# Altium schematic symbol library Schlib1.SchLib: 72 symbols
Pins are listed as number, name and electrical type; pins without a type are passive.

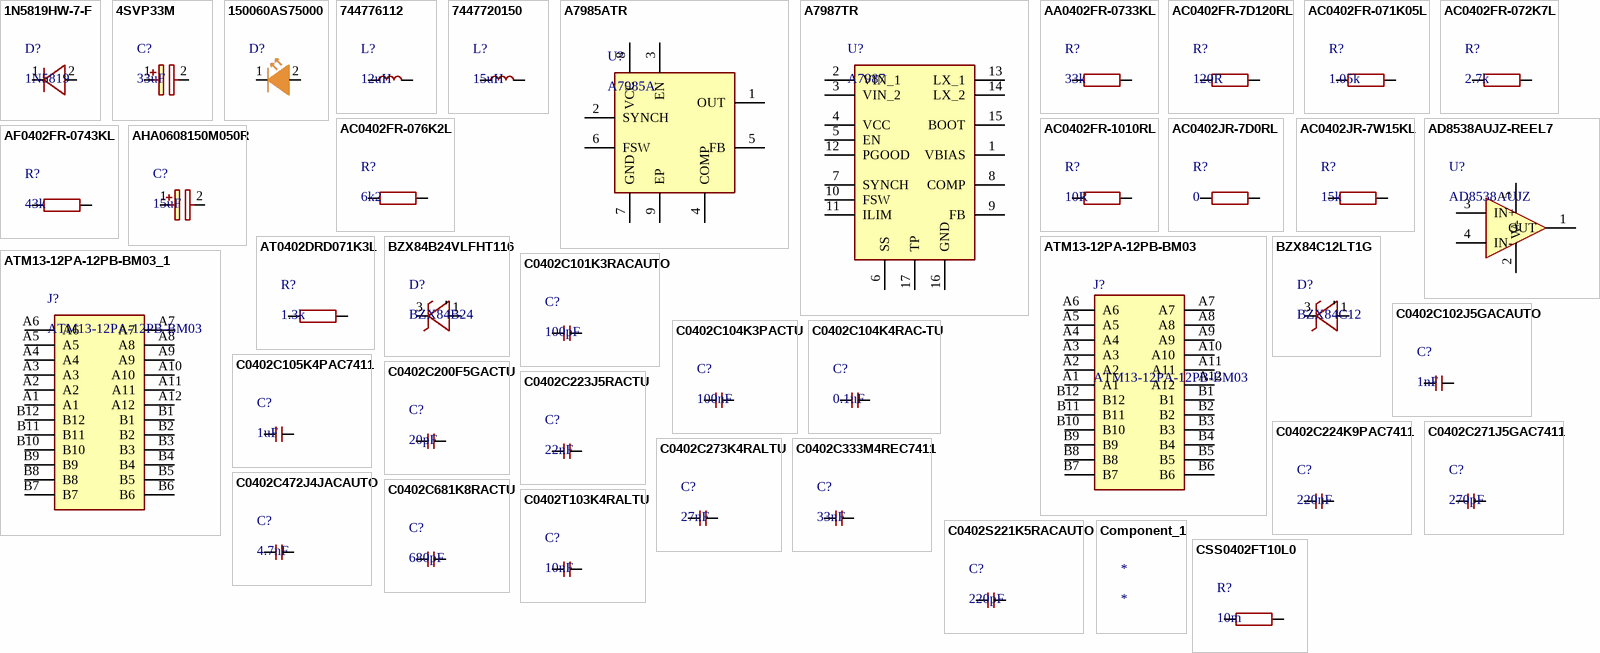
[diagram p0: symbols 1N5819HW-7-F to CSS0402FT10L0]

## 1N5819HW-7-F
designator D?, comment 1N5819
Rectifier Diode, Schottky, 1 Phase, 1 Element, 1A, 40V V(RRM), Silicon; Manufacturer: Diodes; Manufacturer Part Number: 1N5819HW-7-F; Package Body Material: Plastic; Number of Elements: 1; Max Power Dissipation: 450mW; Forward Voltage: 320mV; Non-rep Pk Forward Current-Max: 25A; Time @ Peak Reflow Temperature-Max (s): 40s; Qualification Status: Not Qualified
footprint SOD3716X125N
pins: 1 K, 2 A

## 4SVP33M
designator C?, comment 33uF
Aluminum Electrolytic Capacitor, Polarized, Aluminum (solid Polymer), 4V, 20% +Tol, 20% -Tol, 33uF, Surface Mount, 1717; Manufacturer: Panasonic; Manufacturer Part Number: 4SVP33M; Manufacturer Series: SVP; Dielectric Material: Aluminium; ESR (Equivalent Series Resistance): 200mR; Leakage Current: 66uA; Ripple Current: 37mA; Tan Delta: 0.15
footprint 10SVPS10M
pins: 1 +, 2

## 150060AS75000
designator D?  (value not drawn)
Single Color LED, Amber, Water Clear, 1.1mm; Manufacturer: Wurth Electronics
footprint LED-0603
pins: 1 K, 2 A

## 744776112
designator L?, comment 12uH
General Purpose Inductor, 12uH, 20%, 1 Element, Nickel-zinc Ferrite-Core, SMD, 3935; Manufacturer: Wurth Electronics; Manufacturer Part Number: 744776112; DC Resistance (DCR): 70mR; Inductor Application: POWER INDUCTOR; Channels: 1; Max Current Rating: 2.72A; Shape/Size Description: RECTANGULAR PACKAGE; Shielding: Unshielded; Test Frequency: 1kHz; Self Resonant Frequency: 20MHz
footprint WE-PD2_105455
pins: 1, 2

## 7447720150
designator L?, comment 15uH
Data Line Filter, 1 Function(s), 2.4A; Manufacturer: Wurth Electronics; Manufacturer Part Number: 7447720150; DC Resistance-Max: 45mR; Channels: 1
footprint WE-TI_809589
pins: 1, 2

## A7985ATR
designator U?, comment A7985A
Switching Regulator, Voltage-mode, 3.5A, 275kHz Switching Freq-Max, PDSO8; Manufacturer: STMicroelectronics; Manufacturer Part Number: A7985ATR; Package Body Material: Plastic; Package Equivalence Code: SOP8,.25; Control Technique: PULSE WIDTH MODULATION; Max Supply Voltage: 38V; Min Input Voltage: 4.5V; Nominal Supply Voltage: 12V; Channels: 1; Switcher Configuration: BUCK; Qualification Status: Not Qualified
footprint SOIC127P600X170-9N
pins: 1 OUT, 2 SYNCH, 3 EN, 4 COMP, 5 FB, 6 FSW, 7 GND, 8 VCC, 9 EP

## A7987TR
designator U?, comment A7987
Switching Regulator, Voltage-mode, 4.4A, 1650kHz Switching Freq-Max, PDSO16; Manufacturer: STMicroelectronics; Manufacturer Part Number: A7987TR
footprint SOP65P640X120-17N
pins: 1 VBIAS, 2 VIN_1, 3 VIN_2, 4 VCC, 5 EN, 6 SS, 7 SYNCH, 8 COMP, 9 FB, 10 FSW, 11 ILIM, 12 PGOOD, 13 LX_1, 14 LX_2, 15 BOOT, 16 GND, 17 TP

## AA0402FR-0733KL
designator R?, comment 33k
Fixed Resistor, Metal Glaze/thick Film, 0.0625W, 33000ohm, 50V, 1% +/-Tol, 150ppm/Cel, Surface Mount, 0402; Manufacturer: Yageo; Manufacturer Part Number: AA0402FR-0733KL; Additional Feature: LASER TRIMMABLE; Power: 62.5mW; Rated Temperature: 70°C; Value: 33kR; Temperature Coefficient (ppm/Cel): 150; Package Height: 0.32mm; Package Length: 1mm; Package Width: 0.5mm; Reference Standard: AEC-Q200
footprint R0402
pins: 1, 2

## AC0402FR-7D120RL
designator R?, comment 120R
Fixed Resistor, Metal Glaze/thick Film, 0.0625W, 120ohm, 50V, 1% +/-Tol, -100,100ppm/Cel, 0402; Manufacturer: Yageo; Manufacturer Part Number: AC0402FR-7D120RL; Power: 62.5mW; Package Height: 0.32mm; Package Length: 1mm; Package Width: 0.5mm; Reference Standard: AEC-Q200
footprint R0402
pins: 1, 2

## AC0402FR-071K05L
designator R?, comment 1.05k
Fixed Resistor, Metal Glaze/thick Film, 0.0625W, 1050ohm, 50V, 1% +/-Tol, 100ppm/Cel, Surface Mount, 0402; Manufacturer: Yageo; Manufacturer Part Number: AC0402FR-071K05L; Additional Feature: LASER TRIMMABLE; Power: 62.5mW; Rated Temperature: 70°C; Value: 1.05kR; Temperature Coefficient (ppm/Cel): 100; Package Height: 0.32mm; Package Length: 1mm; Package Width: 0.5mm; Reference Standard: AEC-Q200
footprint R0402
pins: 1, 2

## AC0402FR-072K7L
designator R?, comment 2.7k
Fixed Resistor, Metal Glaze/thick Film, 0.0625W, 2700ohm, 50V, 1% +/-Tol, 100ppm/Cel, Surface Mount, 0402; Manufacturer: Yageo; Manufacturer Part Number: AC0402FR-072K7L; Additional Feature: LASER TRIMMABLE; Power: 62.5mW; Rated Temperature: 70°C; Value: 2.7kR; Temperature Coefficient (ppm/Cel): 100; Package Height: 0.32mm; Package Length: 1mm; Package Width: 0.5mm; Reference Standard: AEC-Q200
footprint R0402
pins: 1, 2

## AC0402FR-076K2L
designator R?, comment 6k2
Fixed Resistor, Metal Glaze/thick Film, 0.0625W, 6200ohm, 50V, 1% +/-Tol, 100ppm/Cel, Surface Mount, 0402; Manufacturer: Yageo; Manufacturer Part Number: AC0402FR-076K2L; Additional Feature: LASER TRIMMABLE; Power: 62.5mW; Rated Temperature: 70°C; Value: 6.2kR; Temperature Coefficient (ppm/Cel): 100; Package Height: 0.32mm; Package Length: 1mm; Package Width: 0.5mm; Reference Standard: AEC-Q200
footprint R0402
pins: 1, 2

## AC0402FR-1010RL
designator R?, comment 10R
Fixed Resistor, Metal Glaze/thick Film, 0.0625W, 10ohm, 50V, 1% +/-Tol, 200ppm/Cel, Surface Mount, 0402; Manufacturer: Yageo; Manufacturer Part Number: AC0402FR-1010RL; Additional Feature: LASER TRIMMABLE; Power: 62.5mW; Rated Temperature: 70°C; Temperature Coefficient (ppm/Cel): 200; Package Height: 0.32mm; Package Length: 1mm; Package Width: 0.5mm; Reference Standard: AEC-Q200
footprint R0402
pins: 1, 2

## AC0402JR-7D0RL
designator R?, comment 0
Fixed Resistor, Metal Glaze/thick Film, 0.0625W, 0ohm, Surface Mount, 0402; Manufacturer: Yageo; Manufacturer Part Number: AC0402JR-7D0RL
footprint R0402
pins: 1, 2

## AC0402JR-7W15KL
designator R?, comment 15k
Chip Resistor Automotive Grade Thick Film 0402 15kOhm 5% Paper T/R; Manufacturer: Yageo; Manufacturer Part Number: AC0402JR-7W15KL
footprint R0402
pins: 1, 2

## AD8538AUJZ-REEL7
designator U?, comment AD8538AUJZ
Operational Amplifier, 1 Func, 30uV Offset-Max, CMOS, PDSO5; Manufacturer: Analog Devices; Manufacturer Part Number: AD8538AUJZ-REEL7; Package Body Material: Plastic; Architecture: VOLTAGE-FEEDBACK; Average Bias Current-Max (IIB): 100pA; Bias Current-Max (IIB) @25C: 25pA; Common-mode Reject Ratio-Nom: 135dB; Frequency Compensation: YES; Neg Supply Voltage Limit-Max: 0V; Channels: 1; Package Equivalence Code: TSOP5/6,.11,37; Power: No; Power Supplies: +-1.35/+-2.5/2.7/5V; Slew Rate: 0.4V/µs; Max Supply Current: 215uA; Supply Voltage Limit-Max: 6V; Nominal Supply Voltage: 5V; Time @ Peak Reflow Temperature-Max (s): 40s; Unity Gain BW-Nom: 430kHz; Voltage Gain-Min: 178000; Qualification Status: Not Qualified
footprint SOT95P280X100-5N
pins: 1 OUT, 2 V-, 3 IN+, 4 IN-, 5 V+

## AF0402FR-0743KL
designator R?, comment 43k
Fixed Resistor, Metal Glaze/thick Film, 0.0625W, 43000ohm, 50V, 1% +/-Tol, 100ppm/Cel, Surface Mount, 0402; Manufacturer: Yageo; Manufacturer Part Number: AF0402FR-0743KL; Additional Feature: ANTI-SULFUR; Power: 62.5mW; Rated Temperature: 70°C; Value: 43kR; Temperature Coefficient (ppm/Cel): 100; Package Height: 0.32mm; Package Length: 1mm; Package Width: 0.5mm; Reference Standard: AEC-Q200
footprint R0402
pins: 1, 2

## AHA0608150M050R
designator C?, comment 15uF
Hybrid Aluminum V-Chip, 15uF, 50V ¦ AVX AHA0608150M050R; Manufacturer: Kyocera AVX
footprint CAPAE660X850N
pins: 1 +, 2

## AT0402DRD071K3L
designator R?, comment 1.3k
Fixed Resistor, Thin Film, 0.0625W, 1300ohm, 50V, 0.5% +/-Tol, 25ppm/Cel, Surface Mount, 0402; Manufacturer: Yageo; Manufacturer Part Number: AT0402DRD071K3L; Additional Feature: HIGH PRECISION; Power: 62.5mW; Rated Temperature: 70°C; Value: 1.3kR; Temperature Coefficient (ppm/Cel): 25; Package Height: 0.3mm; Package Length: 1mm; Package Width: 0.5mm; Reference Standard: AEC-Q200
footprint R0402
pins: 1, 2

## ATM13-12PA-12PB-BM03
designator J?
AMPHENOL SINE/TUCHEL - ATM13-12PA-12PB-BM03 - ATM HEADER  (2) 12 POSITION SIZE 20, A&B KEY  - TIN PLATING 98AC7190; Geometry.Height: 35.4mm
footprint ATM1312PA12PBBM03
pins: A1, A2, A3, A4, A5, A6, A7, A8, A9, A10, A11, A12, B1, B2, B3, B4, B5, B6, B7, B8, B9, B10, B11, B12

## ATM13-12PA-12PB-BM03_1
designator J?, comment ATM13-12PA-12PB-BM03
Combination Line Connector; Manufacturer: Amphenol Sine Systems
footprint ATM1312PA12PBBM03
pins: A1, A2, A3, A4, A5, A6, A7, A8, A9, A10, A11, A12, B1, B2, B3, B4, B5, B6, B7, B8, B9, B10, B11, B12

## BZX84B24VLFHT116
designator D?, comment BZX84B24
Zener Diode, 24V V(Z), 2.08%, 0.25W, Silicon, Unidirectional
footprint TRANS_BZX84_ROM-M
pins: 1 A, 2 NC, 3 K

## BZX84C12LT1G
designator D?, comment BZX84C12
Zener Diode, 12V V(Z), 5.39%, 0.25W, Silicon, Unidirectional, TO-236AB; Manufacturer: ON Semiconductor; Manufacturer Part Number: BZX84C12LT1G; Package Body Material: Plastic; Dynamic Impedance-Max: 25R; Number of Elements: 1; Max Power Dissipation: 250mW; Test Current: 5mA; Additional Feature: UL RECOGNIZED; Time @ Peak Reflow Temperature-Max (s): 40s; Qualification Status: Not Qualified
footprint SOT96P237X111-3N
pins: 1 A, 2 NC, 3 K

## C0402C101K3RACAUTO
designator C?, comment 100pF
Multilayer Ceramic Capacitors MLCC - SMD/SMT 25V 100pF X7R 0402 10% AEC-Q200; Manufacturer: KEMET; Manufacturer Part Number: C0402C101K3RACAUTO
footprint C0402
pins: 1, 2

## C0402C102J5GACAUTO
designator C?, comment 1nF
Ceramic Capacitor, Multilayer, Ceramic, 50V, 5% +Tol, 5% -Tol, C0G, 30ppm/Cel TC, 0.001uF, Surface Mount, 0402; Manufacturer: KEMET; Manufacturer Part Number: C0402C102J5GACAUTO; Multilayer: Yes; Reference Standard: AEC-Q200
footprint C0402
pins: 1, 2

## C0402C104K3PACTU
designator C?, comment 100nF
Ceramic Capacitor, Multilayer, Ceramic, 25V, 10% +Tol, 10% -Tol, X5R, 15% TC, 0.1uF, Surface Mount, 0402; Manufacturer: KEMET; Manufacturer Part Number: C0402C104K3PACTU; Multilayer: Yes
footprint C0402
pins: 1, 2

## C0402C104K4RAC-TU
designator C?, comment 0.1uF
100nF ±10% 16V X7R 0402 Multilayer Ceramic Capacitors MLCC - SMD/SMT RoHS; Manufacturer: KEMET; Manufacturer Part Number: C0402C104K4RAC-TU
footprint C0402
pins: 1, 2

## C0402C105K4PAC7411
designator C?, comment 1uF
Ceramic Capacitor, Multilayer, Ceramic, 16V, 10% +Tol, 10% -Tol, X5R, 15% TC, 1uF, Surface Mount, 0402; Manufacturer: KEMET; Manufacturer Part Number: C0402C105K4PAC7411; Multilayer: Yes
footprint C0402
pins: 1, 2

## C0402C200F5GACTU
designator C?, comment 20pF
Ceramic Capacitor, Multilayer, Ceramic, 50V, 1% +Tol, 1% -Tol, C0G, 30ppm/Cel TC, 0.00002uF, Surface Mount, 0402; Manufacturer: KEMET; Manufacturer Part Number: C0402C200F5GACTU; Multilayer: Yes
footprint C0402
pins: 1, 2

## C0402C223J5RACTU
designator C?, comment 22nF
Ceramic Capacitor, Multilayer, Ceramic, 50V, 5% +Tol, 5% -Tol, X7R, 15% TC, 0.022uF, Surface Mount, 0402; Manufacturer: KEMET; Manufacturer Part Number: C0402C223J5RACTU; Multilayer: Yes
footprint C0402
pins: 1, 2

## C0402C224K9PAC7411
designator C?, comment 220nF
Ceramic Capacitor, Multilayer, Ceramic, 6.3V, 10% +Tol, 10% -Tol, X5R, 15% TC, 0.22uF, Surface Mount, 0402; Manufacturer: KEMET; Manufacturer Part Number: C0402C224K9PAC7411; Multilayer: Yes
footprint C0402
pins: 1, 2

## C0402C271J5GAC7411
designator C?, comment 270pF
Ceramic Capacitor, Multilayer, Ceramic, 50V, 5% +Tol, 5% -Tol, C0G, 30ppm/Cel TC, 0.00027uF, Surface Mount, 0402; Manufacturer: KEMET; Manufacturer Part Number: C0402C271J5GAC7411; Multilayer: Yes
footprint C0402
pins: 1, 2

## C0402C273K4RALTU
designator C?, comment 27nF
.027Uf 16.0V Rohs Compliant: No; Manufacturer: KEMET; Manufacturer Part Number: C0402C273K4RALTU
footprint C0402
pins: 1, 2

## C0402C333M4REC7411
designator C?, comment 33nF
Ceramic Capacitor, Multilayer, Ceramic, 16V, 20% +Tol, 20% -Tol, X7R, 15% TC, 0.033uF, Surface Mount, 0402; Manufacturer: KEMET; Manufacturer Part Number: C0402C333M4REC7411
footprint C0402
pins: 1, 2

## C0402C472J4JACAUTO
designator C?, comment 4.7nF
Cap Ceramic 0.0047uF 16V U2J 5% Pad SMD 0402 125C T/R; Manufacturer: KEMET; Manufacturer Part Number: C0402C472J4JACAUTO
footprint C0402
pins: 1, 2

## C0402C681K8RACTU
designator C?, comment 680pF
Ceramic Capacitor, Multilayer, Ceramic, 10V, 10% +Tol, 10% -Tol, X7R, 15% TC, 0.00068uF, Surface Mount, 0402; Manufacturer: KEMET; Manufacturer Part Number: C0402C681K8RACTU; Multilayer: Yes
footprint C0402
pins: 1, 2

## C0402S221K5RACAUTO
designator C?, comment 220pF
Ceramic Capacitor, Multilayer, Ceramic, 50V, 10% +Tol, 10% -Tol, X7R, 15% TC, 0.00022uF, Surface Mount, 0402; Manufacturer: KEMET; Manufacturer Part Number: C0402S221K5RACAUTO
footprint C0402
pins: 1, 2

## C0402T103K4RALTU
designator C?, comment 10nF
Ceramic Capacitor, Multilayer, Ceramic, 16V, 10% +Tol, 10% -Tol, X7R, 15% TC, 0.01uF, Surface Mount, 0402; Manufacturer: KEMET; Manufacturer Part Number: C0402T103K4RALTU; Multilayer: Yes
footprint C0402
pins: 1, 2

## Component_1
designator *

## CSS0402FT10L0
designator R?, comment 10m
Fixed Resistor, Metal Alloy, 0.33W, 0.01ohm, 1% +/-Tol, 100ppm/Cel, Surface Mount, 0402; Manufacturer: Stackpole Electronics; Manufacturer Part Number: CSS0402FT10L0
footprint CSS0402FT10L0
pins: 1, 2

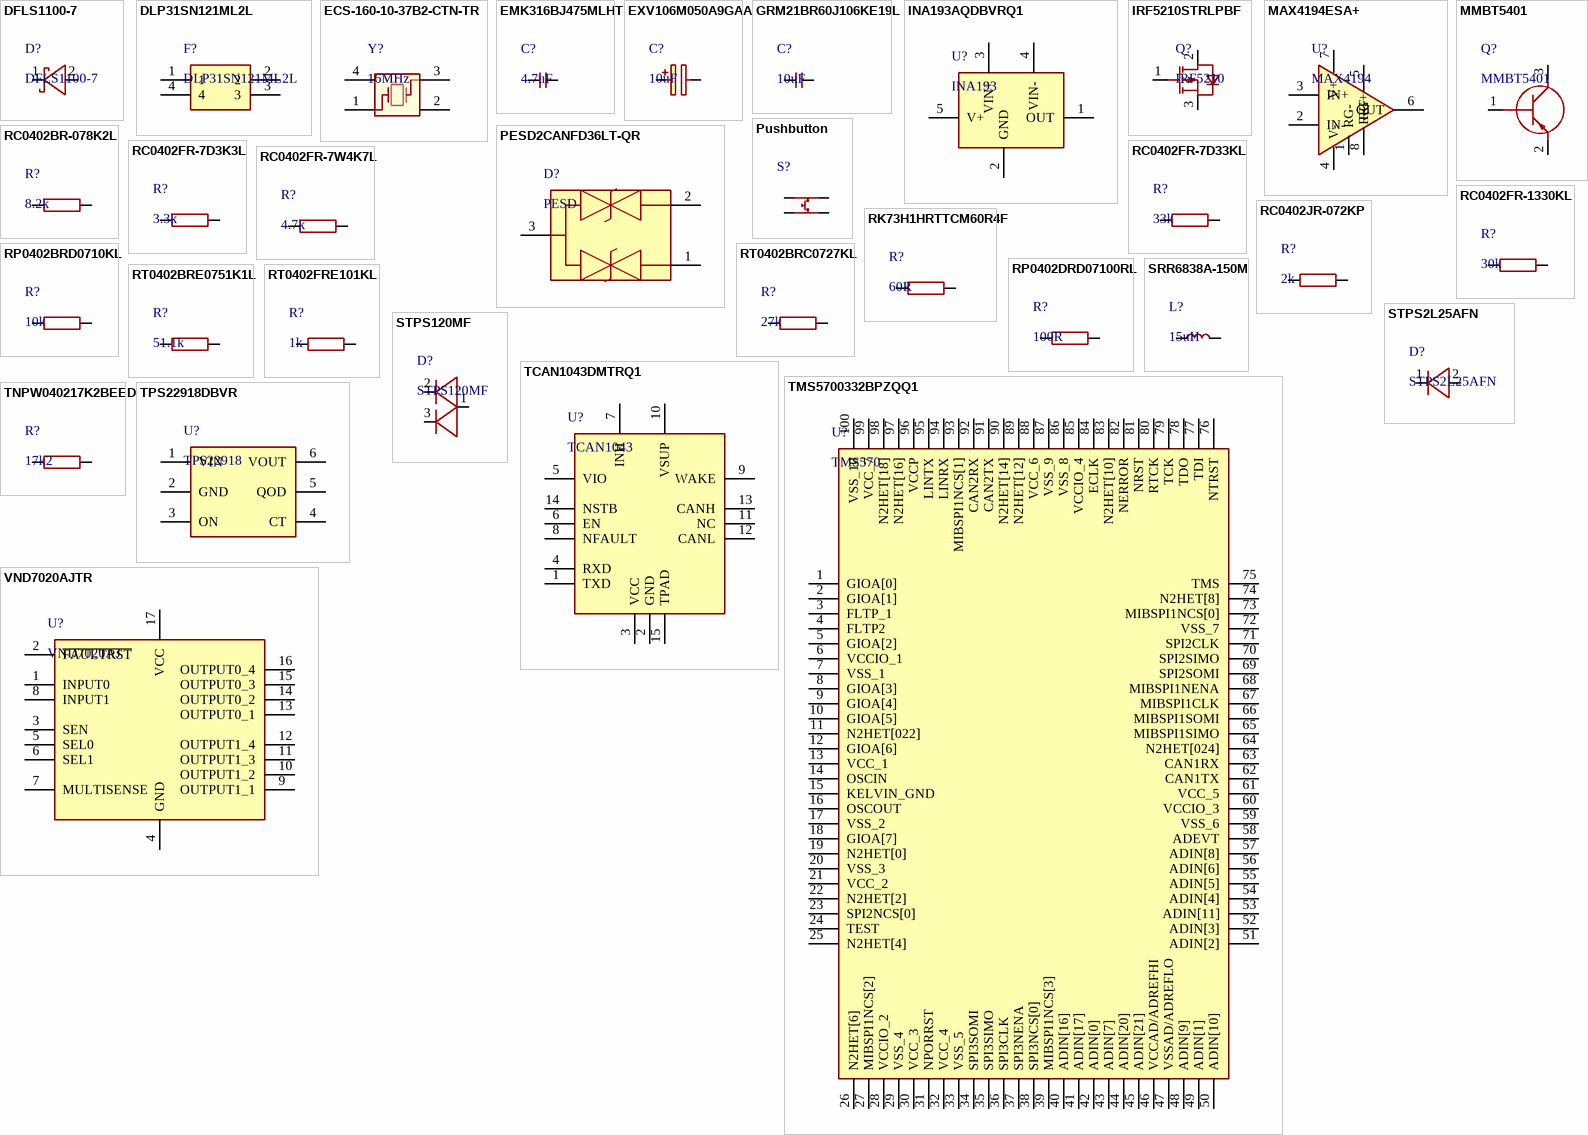
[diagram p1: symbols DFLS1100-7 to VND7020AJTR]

## DFLS1100-7
designator D?
Rectifier Diode, Schottky, 1 Phase, 1 Element, 1A, 100V V(RRM), Silicon; Manufacturer: Diodes; Package Body Material: Plastic; Case Connection: CATHODE; Forward Voltage: 770mV; Non-rep Pk Forward Current-Max: 40A; Number of Elements: 1; Time @ Peak Reflow Temperature-Max (s): 40s; Qualification Status: Not Qualified
footprint DFLS110
pins: 1 K, 2 A

## DLP31SN121ML2L
designator F?
Data Line Filter, 2 Function(s), 16V, 0.1A, 4 Pin(s); Manufacturer: Murata; DC Resistance-Max: 2R; Insulation Resistance-Min: 100MR; Channels: 2; Output Impedance: 120R; Current Rating: 100mA
footprint DLP31SN121ML2B
pins: 1, 2, 3, 4

## ECS-160-10-37B2-CTN-TR
designator Y?, comment 16MHz
Crystal 16MHz 10pF 4-Pin SMD ECX-1637B2 T/R; Manufacturer: ECS International; Manufacturer Part Number: ECS-160-10-37B2-CTN-TR
footprint ECS1601037B2CTNTR
pins: 1, 2, 3, 4

## EMK316BJ475MLHT
designator C?, comment 4.7uF
Ceramic Capacitor, Multilayer, Ceramic, 16V, 20% +Tol, 20% -Tol, X5R, 15% TC, 4.7uF, Surface Mount, 1206; Manufacturer: Taiyo Yuden; Manufacturer Part Number: EMK316BJ475MLHT
footprint CAPC3216X180N
pins: 1, 2

## EXV106M050A9GAA
designator C?, comment 10uF
Aluminum Electrolytic Capacitor, Polarized, Aluminum (wet), 50V, 20% +Tol, 20% -Tol, 10uF, Surface Mount, 2626; Manufacturer: KEMET; Manufacturer Part Number: EXV106M050A9GAA; Dielectric Material: Aluminium; ESR (Equivalent Series Resistance): 2.6R; Leakage Current: 5uA; Ripple Current: 98mA; Tan Delta: 0.12
footprint CAPAE660X565N
pins: 1 +, 2

## GRM21BR60J106KE19L
designator C?, comment 10uF
Ceramic Capacitor, Multilayer, Ceramic, 6.3V, 10% +Tol, 10% -Tol, X5R, 15% TC, 10uF, Surface Mount, 0805; Manufacturer: Murata; Manufacturer Part Number: GRM21BR60J106KE19L; Multilayer: Yes
footprint CAPC2012X145N
pins: 1, 2

## INA193AQDBVRQ1
designator U?, comment INA193
Operational Amplifier, 1 Func, PDSO5; Manufacturer: Texas Instruments; Manufacturer Part Number: INA193AQDBVRQ1; Package Body Material: Plastic; Adjustable Threshold: No; Throw Configuration: POWER SUPPLY SUPPORT CIRCUIT; Number of Channels: 1; Package Equivalence Code: TSOP5/6,.11,37; Power Supplies: 12V; Supply Current-Max (Isup): 1.25mA; Max Supply Voltage: 18V; Min Supply Voltage: 2.7V; Qualification Status: Not Qualified
footprint SOT95P280X145-5N
pins: 1 OUT, 2 GND, 3 VIN+, 4 VIN-, 5 V+

## IRF5210STRLPBF
designator Q?, comment IRF5210
Zener Diode, 24V V(Z), 2.08%, 0.25W, Silicon, Unidirectional; Manufacturer: Infineon; Manufacturer Part Number: IRF5210STRLPBF; Package Body Material: Plastic; Polarity/Channel Type: P-CHANNEL; Avalanche Energy Rating (Eas): 120mJ; Case Connection: DRAIN; Drain Current-Max (ID): 38A; Drain-source On Resistance-Max: 60mR; DS Breakdown Voltage-Min: 100V; FET Technology: METAL-OXIDE SEMICONDUCTOR; Number of Elements: 1; Operating Mode: ENHANCEMENT MODE; Pulsed Drain Current-Max (IDM): 140A; Transistor Application: SWITCHING; Time @ Peak Reflow Temperature-Max (s): 30s; Power Dissipation-Max (Abs): 170W; JEDEC-95 Code: TO-263AB; Qualification Status: Not Qualified
footprint TO254P1528X508-4_3N-V1 (TO,2.54mm pitch;3 pin,15.28mm L X 9.00mm W X 5.08mm H body)
pins: 1 GATE, 2 DRAIN, 3 SOURCE

## MAX4194ESA+
designator U?, comment MAX4194
Instrumentation Amplifier, 1 Func, 690uV Offset-Max, 0.25MHz Band Width, PDSO8; Manufacturer: Maxim; Manufacturer Part Number: MAX4194ESA+; Package Body Material: Plastic; Average Bias Current-Max (IIB): 20nA; Bandwidth (3dB)-Nom: 250kHz; Common Mode Rejection Ratio-Min: 73dB; Input Offset Current-Max (IIO): 3nA; Channels: 1; Package Equivalence Code: SOP8,.25; Power Supplies: +-1.35/+-3.75/2.7/7.5V; Slew Rate: 0.06V/µs; Max Supply Current: 110uA; Supply Voltage Limit-Max: 8V; Nominal Supply Voltage: 5V; Time @ Peak Reflow Temperature-Max (s): 30s; Voltage Gain-Max: 10000; Qualification Status: Not Qualified
footprint SOIC127P600X175-8N
pins: 1 RG-, 2 IN-, 3 IN+, 4 V-, 5 REF, 6 OUT, 7 V+, 8 RG+

## MMBT5401
designator Q?
Small Signal Bipolar Transistor, 0.6A I(C), 150V V(BR)CEO, 1-Element, PNP, Silicon, TO-236; Manufacturer: Diotec; Package Body Material: Plastic; Max Collector Current: 600mA; DC Current Gain-Min (hFE): 50; Number of Elements: 1; Frequency: 100MHz; Qualification Status: Not Qualified
footprint SOT95P240X120-3N
pins: 1 B, 2 E, 3 C

## PESD2CANFD36LT-QR
designator D?, comment PESD
ESD Protection Diodes / TVS Diodes ESD protection for in-vehicle networks; Manufacturer: Nexperia; Manufacturer Part Number: PESD2CANFD36LT-QR
footprint PESD2CANFD36LTQR
pins: 1 K1, 2 K2, 3 CC

## Pushbutton
designator S?
BUTON MINI 6X6X5, 4 PINI
footprint Pushbutton
pins: 1, 2, 3, 4

## RC0402BR-078K2L
designator R?, comment 8.2k
Fixed Resistor, Metal Glaze/thick Film, 0.0625W, 8200ohm, 50V, 0.1% +/-Tol, 100ppm/Cel, Surface Mount, 0402; Manufacturer: Yageo; Manufacturer Part Number: RC0402BR-078K2L
footprint R0402
pins: 1, 2

## RC0402FR-7D3K3L
designator R?, comment 3.3k
Fixed Resistor, Metal Glaze/thick Film, 0.0625W, 3300ohm, 50V, 1% +/-Tol, 100ppm/Cel, Surface Mount, 0402; Manufacturer: Yageo; Manufacturer Part Number: RC0402FR-7D3K3L; Additional Feature: LASER TRIMMABLE; Power: 62.5mW; Rated Temperature: 70°C; Value: 3.3kR; Temperature Coefficient (ppm/Cel): 100; Package Height: 0.35mm; Package Length: 1mm; Package Width: 0.5mm
footprint R0402
pins: 1, 2

## RC0402FR-7D33KL
designator R?, comment 33k
Fixed Resistor, Metal Glaze/thick Film, 0.0625W, 33000ohm, 50V, 1% +/-Tol, 100ppm/Cel, Surface Mount, 0402; Manufacturer: Yageo; Manufacturer Part Number: RC0402FR-7D33KL
footprint R0402
pins: 1, 2

## RC0402FR-7W4K7L
designator R?, comment 4.7k
Fixed Resistor, Metal Glaze/thick Film, 0.125W, 4700ohm, 50V, 1% +/-Tol, 200ppm/Cel, Surface Mount, 0402; Manufacturer: Yageo; Manufacturer Part Number: RC0402FR-7W4K7L; Additional Feature: LASER TRIMMABLE; Power: 125mW; Rated Temperature: 70°C; Value: 4.7kR; Temperature Coefficient (ppm/Cel): 200; Package Height: 0.35mm; Package Length: 1mm; Package Width: 0.5mm
footprint R0402
pins: 1, 2

## RC0402FR-1330KL
designator R?, comment 30k
Fixed Resistor, Metal Glaze/thick Film, 0.0625W, 30000ohm, 50V, 1% +/-Tol, 100ppm/Cel, Surface Mount, 0402; Manufacturer: Yageo; Manufacturer Part Number: RC0402FR-1330KL; Additional Feature: LASER TRIMMABLE; Power: 62.5mW; Rated Temperature: 70°C; Value: 30kR; Temperature Coefficient (ppm/Cel): 100; Package Height: 0.35mm; Package Length: 1mm; Package Width: 0.5mm
footprint R0402
pins: 1, 2

## RC0402JR-072KP
designator R?, comment 2k
Fixed Resistor, Metal Glaze/thick Film, 0.0625W, 2000ohm, 50V, 5% +/-Tol, 150ppm/Cel, Surface Mount, 0402; Manufacturer: Yageo; Manufacturer Part Number: RC0402JR-072KP
footprint R0402
pins: 1, 2

## RK73H1HRTTCM60R4F
designator R?, comment 60R
Fixed Resistor, Metal Glaze/thick Film, 0.05W, 60.4ohm, 25V, 1% +/-Tol, 300ppm/Cel, Surface Mount, 0201; Manufacturer: KOA Speer; Manufacturer Part Number: RK73H1HRTTCM60R4F
footprint R0201
pins: 1, 2

## RP0402BRD0710KL
designator R?, comment 10k
Resistor, 10K, 0.1%, 0.063W, THIN FILM, 0402;; Manufacturer: Yageo; Manufacturer Part Number: RP0402BRD0710KL
footprint R0402
pins: 1, 2

## RP0402DRD07100RL
designator R?, comment 100R
Res, 100R, 0.5%, 0.063W, Thin Film, 0402 Rohs Compliant: Yes; Manufacturer: Yageo; Manufacturer Part Number: RP0402DRD07100RL
footprint R0402
pins: 1, 2

## RT0402BRC0727KL
designator R?, comment 27k
Fixed Resistor, Thin Film, 0.0625W, 27000ohm, 50V, 0.1% +/-Tol, 15ppm/Cel, Surface Mount, 0402; Manufacturer: Yageo; Manufacturer Part Number: RT0402BRC0727KL; Additional Feature: HIGH PRECISION; Power: 62.5mW; Rated Temperature: 70°C; Value: 27kR; Temperature Coefficient (ppm/Cel): 15; Package Height: 0.3mm; Package Length: 1mm; Package Width: 0.5mm
footprint R0402
pins: 1, 2

## RT0402BRE0751K1L
designator R?, comment 51.1k
Fixed Resistor, Thin Film, 0.0625W, 51100ohm, 50V, 0.1% +/-Tol, 50ppm/Cel, Surface Mount, 0402; Manufacturer: Yageo; Manufacturer Part Number: RT0402BRE0751K1L; Additional Feature: HIGH PRECISION; Power: 62.5mW; Rated Temperature: 70°C; Value: 51.1kR; Temperature Coefficient (ppm/Cel): 50; Package Height: 0.3mm; Package Length: 1mm; Package Width: 0.5mm
footprint R0402
pins: 1, 2

## RT0402FRE101KL
designator R?, comment 1k
Fixed Resistor, Thin Film, 0.0625W, 1000ohm, 50V, 1% +/-Tol, 50ppm/Cel, Surface Mount, 0402; Manufacturer: Yageo; Manufacturer Part Number: RT0402FRE101KL
footprint R0402
pins: 1, 2

## SRR6838A-150M
designator L?, comment 15uH
Power Inductors - SMD Ind,6.8x6.8x3.8mm,15uH+/-20%,2.1A,; Manufacturer: Bourns; Manufacturer Part Number: SRR6838A-150M
footprint INDPM6868X420N
pins: 1, 2

## STPS2L25AFN
designator D?
Rectifier Diode; Manufacturer: STMicroelectronics
footprint SODFL5226X110N
pins: 1 K, 2 A

## STPS120MF
designator D?
Rectifier Diode, Schottky, 1 Phase, 1 Element, 1A, 20V V(RRM), Silicon, DO-222AA; Manufacturer: STMicroelectronics; Package Body Material: Plastic; Case Connection: CATHODE; Forward Voltage: 410mV; Non-rep Pk Forward Current-Max: 50A; Number of Elements: 1; Qualification Status: Not Qualified
footprint STPS120MF
pins: 1 A, 2 K, 3 K

## TCAN1043DMTRQ1
designator U?, comment TCAN1043
Ethernet Transceiver, 1-Trnsvr, PDSO14; Manufacturer: Texas Instruments; Manufacturer Part Number: TCAN1043DMTRQ1
footprint SON65P300X450X90-15N
pins: 1 TXD, 2 GND, 3 VCC, 4 RXD, 5 VIO, 6 EN, 7 INH, 8 NFAULT, 9 WAKE, 10 VSUP, 11 NC, 12 CANL, 13 CANH, 14 NSTB, 15 TPAD

## TMS5700332BPZQQ1
designator U?, comment TMS570
RISC Microcontroller, 32-Bit, FLASH, CORTEX-R4F CPU, 80MHz, CMOS, PQFP100; Manufacturer: Texas Instruments; Manufacturer Part Number: TMS5700332BPZQQ1
footprint QFP50P1600X1600X160-100N
pins: 1 GIOA[0], 2 GIOA[1], 3 FLTP_1, 4 FLTP2, 5 GIOA[2], 6 VCCIO_1, 7 VSS_1, 8 GIOA[3], 9 GIOA[4], 10 GIOA[5], 11 N2HET[022], 12 GIOA[6], 13 VCC_1, 14 OSCIN, 15 KELVIN_GND, 16 OSCOUT, 17 VSS_2, 18 GIOA[7], 19 N2HET[0], 20 VSS_3, 21 VCC_2, 22 N2HET[2], 23 SPI2NCS[0], 24 TEST, 25 N2HET[4], 26 N2HET[6], 27 MIBSPI1NCS[2], 28 VCCIO_2, 29 VSS_4, 30 VCC_3, 31 NPORRST, 32 VCC_4, 33 VSS_5, 34 SPI3SOMI, 35 SPI3SIMO, 36 SPI3CLK, 37 SPI3NENA, 38 SPI3NCS[0], 39 MIBSPI1NCS[3], 40 ADIN[16], 41 ADIN[17], 42 ADIN[0], 43 ADIN[7], 44 ADIN[20], 45 ADIN[21], 46 VCCAD/ADREFHI, 47 VSSAD/ADREFLO, 48 ADIN[9], 49 ADIN[1], 50 ADIN[10], 51 ADIN[2], 52 ADIN[3], 53 ADIN[11], 54 ADIN[4], 55 ADIN[5], 56 ADIN[6], 57 ADIN[8], 58 ADEVT, 59 VSS_6, 60 VCCIO_3, 61 VCC_5, 62 CAN1TX, 63 CAN1RX, 64 N2HET[024], 65 MIBSPI1SIMO, 66 MIBSPI1SOMI, 67 MIBSPI1CLK, 68 MIBSPI1NENA, 69 SPI2SOMI, 70 SPI2SIMO, 71 SPI2CLK, 72 VSS_7, 73 MIBSPI1NCS[0], 74 N2HET[8], 75 TMS, 76 NTRST, 77 TDI, 78 TDO, 79 TCK, 80 RTCK, 81 NRST, 82 NERROR, 83 N2HET[10], 84 ECLK, 85 VCCIO_4, 86 VSS_8, 87 VSS_9, 88 VCC_6, 89 N2HET[12], 90 N2HET[14], 91 CAN2TX, 92 CAN2RX, 93 MIBSPI1NCS[1], 94 LINRX, 95 LINTX, 96 VCCP, 97 N2HET[16], 98 N2HET[18], 99 VCC_7, 100 VSS_10

## TNPW040217K2BEED
designator R?, comment 17k2
Fixed Resistor, Thin Film, 0.063W, 17200ohm, 50V, 0.1% +/-Tol, 25ppm/Cel, Surface Mount, 0402; Manufacturer: Vishay Dale; Manufacturer Part Number: TNPW040217K2BEED; Manufacturer Series: TNPW; Power: 63mW; Rated Temperature: 70°C; Value: 17.2kR; Temperature Coefficient (ppm/Cel): 25
footprint R0402
pins: 1, 2

## TPS22918DBVR
designator U?, comment TPS22918
Power Supply Support Circuit, Fixed, 1 Channel, PDSO6; Manufacturer: Texas Instruments; Manufacturer Part Number: TPS22918DBVR; Package Body Material: Plastic; Adjustable Threshold: No; Number of Channels: 1; Package Equivalence Code: TSOP6,.11,37; Max Supply Voltage: 5.5V; Min Supply Voltage: 0V; Nominal Supply Voltage: 1V
footprint SOT95P280X145-6N
pins: 1 VIN, 2 GND, 3 ON, 4 CT, 5 QOD, 6 VOUT

## VND7020AJTR
designator U?, comment VND7020AJ
Buffer/Inverter Based Peripheral Driver, PDSO16; Manufacturer: STMicroelectronics; Manufacturer Part Number: VND7020AJTR; Package Body Material: Plastic; Built-in Protections: Over Current,Over Voltage,Under Voltage,TRANSIENT,THERMAL; Interface IC Type: BUFFER OR INVERTER BASED PERIPHERAL DRIVER; Channels: 1; Output Current Flow Direction: SINK; Max Supply Voltage: 28V; Min Supply Voltage: 4V; Nominal Supply Voltage: 13V; Turn-Off Delay Time: 100us; Turn-On Delay Time: 120us
footprint SOP50P600X170-17N
pins: 1 INPUT0, 2 ~{FAULTRST}, 3 SEN, 4 GND, 5 SEL0, 6 SEL1, 7 MULTISENSE, 8 INPUT1, 9 OUTPUT1_1, 10 OUTPUT1_2, 11 OUTPUT1_3, 12 OUTPUT1_4, 13 OUTPUT0_1, 14 OUTPUT0_2, 15 OUTPUT0_3, 16 OUTPUT0_4, 17 VCC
